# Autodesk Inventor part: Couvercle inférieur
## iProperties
Author: Philippe
Shininess: 61.0
Angle Display Precision: 2
Document Length Units: 11269
Document Angle Units: 11283
Document Time Units: 11279
Document Mass Units: 11290
Document Length Units Precision: 3
Document Angle Units Precision: 2
Compacted: False
PropertySet Name: _Private Model Information
Created: 2002-01
Part Number: Couvercle inférieur
Material: Par défaut
Document SubType Name: Modélisation
Designer: Philippe
Control State: 0
Master: False
Checked Out: False
PropertySet Name: Design Tracking Control
Density: 0.0
Volumn: 0.0
Area: 0.0
PropertySet Name: Model Information
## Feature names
1. Extrusion1
2. Congé1 [Fillet]
3. Coque1
4. Extrusion2
5. Congé2 [Fillet]
